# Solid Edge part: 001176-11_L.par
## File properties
Last saved by: morva
Revision: 82
Accuracy: 0.990
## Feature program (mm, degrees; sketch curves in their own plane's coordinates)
body "unnamed Body 1"
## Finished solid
Body 1: solid body, 36 faces, 82 edges, 50 vertices.
  Faces by surface: cone 16, plane 10, cylinder 6, torus 4
  Edges by curve: circle 36, curve on surface 24, line 16, spline 6
Bounding box of the edges (mm; curved faces can reach further): 8.874 x 7.413 x 9.448, from (503.415, 412.5802, -104.5987) to (512.2889, 419.9933, -95.1503).
Cylindrical faces by radius (mm): R2 x2, R2.5 x2, R3.75 x2
Conical faces (half-angle, radius in mm at the cone's reference point): 45 deg R2.5 x2, 45 deg R4.6225 x14
Toroidal faces (ring radius, tube radius in mm): R3.25 r0.5 x2, R3.95 r0.2 x2
Planar faces by outward normal: oblique 10
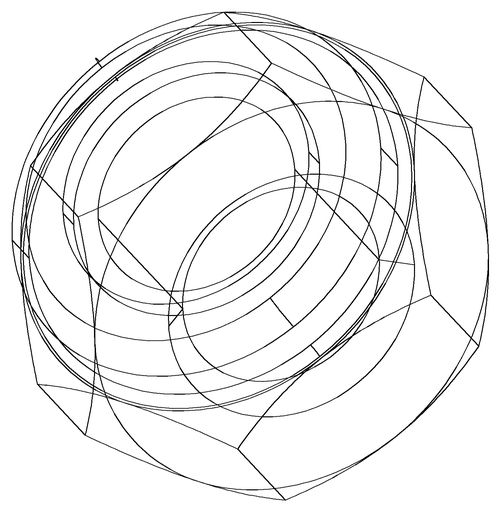
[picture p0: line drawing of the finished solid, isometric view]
